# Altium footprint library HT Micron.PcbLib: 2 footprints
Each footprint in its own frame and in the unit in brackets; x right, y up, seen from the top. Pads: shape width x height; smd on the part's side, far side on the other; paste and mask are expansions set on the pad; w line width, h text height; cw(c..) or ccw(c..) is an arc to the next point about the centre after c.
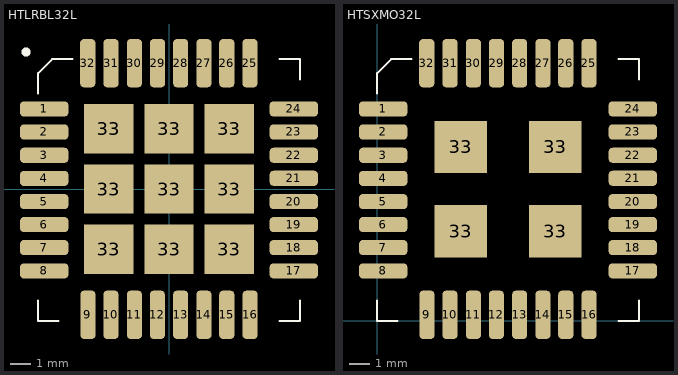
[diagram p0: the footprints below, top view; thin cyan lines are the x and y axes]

## HTLRBL32L [mm] "HTLRBL32L SiP"
pads (41):
  rrect50% 2.4x0.75 smd: 1(-6.2,3.975) 2(-6.2,2.832) 3(-6.2,1.675) 4(-6.2,0.525) 5(-6.2,-0.625) 6(-6.2,-1.768) 7(-6.2,-2.911) 8(-6.2,-4.07) 17(6.2,-4.07) 18(6.2,-2.911) 19(6.2,-1.768) 20(6.2,-0.625) 21(6.2,0.532) 22(6.2,1.675) 23(6.2,2.832) 24(6.2,3.975)
  rrect50% 0.75x2.4 smd: 9(-4.025,-6.25) 10(-2.882,-6.25) 11(-1.72,-6.25) 12(-0.58,-6.25) 13(0.58,-6.25) 14(1.73,-6.25) 15(2.87,-6.25) 16(4.03,-6.25) 25(4.02,6.25) 26(2.87,6.25) 27(1.73,6.25) 28(0.58,6.25) 29(-0.57,6.25) 30(-1.72,6.25) 31(-2.88,6.25) 32(-4.035,6.25)
  rect 2.45x2.45 smd: 33(-3,-3) 33(-3,0) 33(-3,3) 33(0,-3) 33(0,0) 33(0,3) 33(3,-3) 33(3,0) 33(3,3)
Top Overlay:
  circle w0.254: c-7.1,6.8 r0.1
  lines w0.1: -6.5,-5.55 -6.5,-6.55 -5.5,-6.55 ; -6.5,4.75 -6.5,5.75 -5.8,6.45 -4.8,6.45 ; 5.5,-6.55 6.5,-6.55 6.5,-5.55 ; 5.5,6.45 6.5,6.45 6.5,5.45
3D body: height 2, standoff 0.25, extent -6.54,-6.59 6.54,6.491

## HTSXMO32L [mm] "HTSXMO32L SiP"
pads (36):
  rrect50% 2.4x0.75 smd: 1(0.3,10.525) 2(0.3,9.382) 3(0.3,8.225) 4(0.3,7.075) 5(0.3,5.925) 6(0.3,4.782) 7(0.3,3.639) 8(0.3,2.48) 17(12.7,2.48) 18(12.7,3.639) 19(12.7,4.782) 20(12.7,5.925) 21(12.7,7.082) 22(12.7,8.225) 23(12.7,9.382) 24(12.7,10.525)
  rrect50% 0.75x2.4 smd: 9(2.475,0.3) 10(3.618,0.3) 11(4.78,0.3) 12(5.92,0.3) 13(7.08,0.3) 14(8.23,0.3) 15(9.37,0.3) 16(10.53,0.3) 25(10.52,12.8) 26(9.37,12.8) 27(8.23,12.8) 28(7.08,12.8) 29(5.93,12.8) 30(4.78,12.8) 31(3.62,12.8) 32(2.465,12.8)
  rect 2.6x2.6 smd: 33(4.15,4.445) 33(4.15,8.636) 33(8.849,4.445) 33(8.849,8.636)
Top Overlay:
  lines w0.1: 0,1 0,0 1,0 ; 0,11.3 0,12.3 0.7,13 1.7,13 ; 12,0 13,0 13,1 ; 12,13 13,13 13,12
3D body: height 2, standoff 0.25, extent -0.041,-0.041 13.04,13.04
